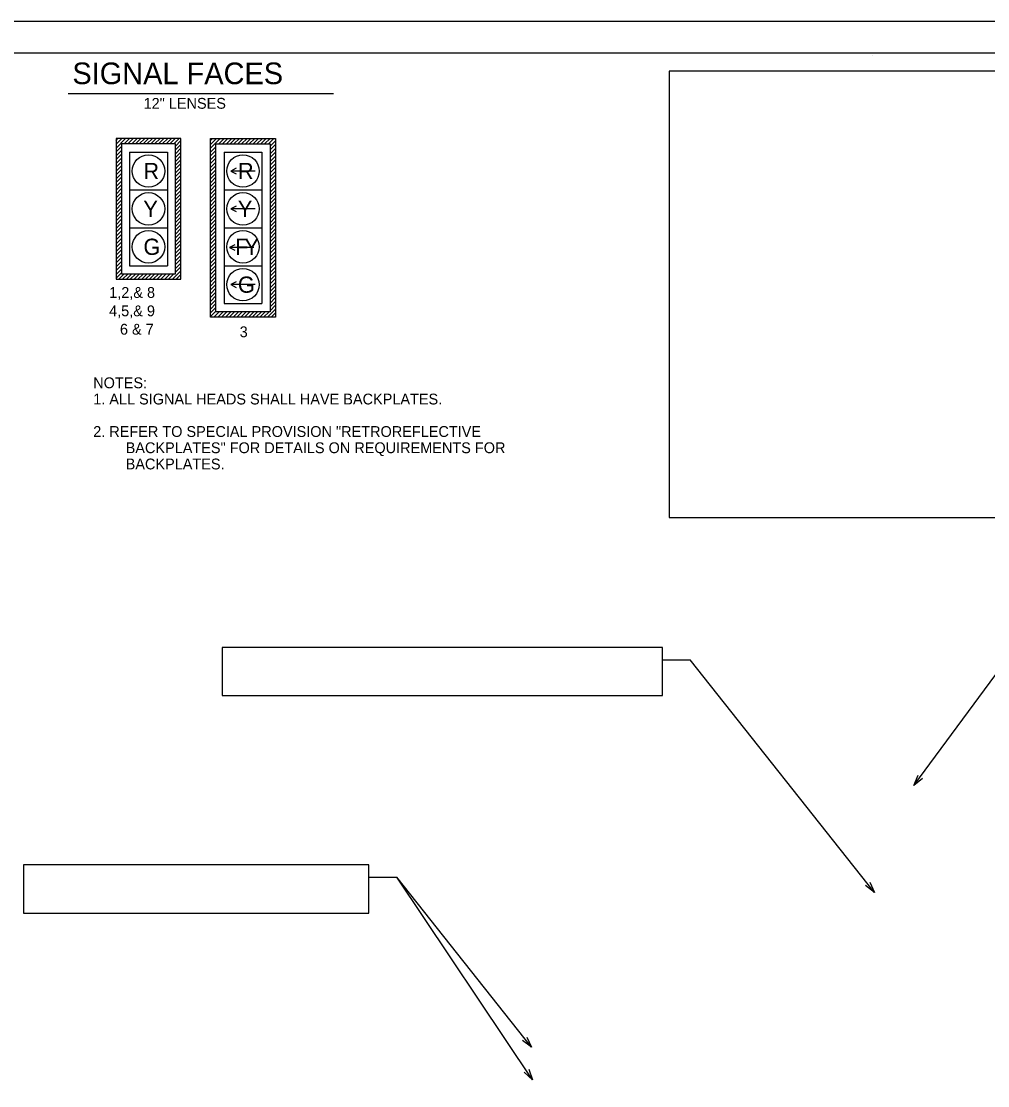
# Model space of a CAD drawing. Extents: x 1736833 to 1738623, y 544707 to 545544.
# Drawn here: x 1737803.3 to 1738160.6, y 544953.4 to 545346.8 of the extents above; entities that cross this region are included whole.
import ezdxf

# ---------------------------------------------------------------- set-up
doc = ezdxf.new("R2010")
doc.units = 0
for name, color, linetype in [('R_Border', 7, 'Continuous'), ('R_Draft', 7, 'Continuous'), ('R_No Plot', 7, 'Continuous'), ('T_Drafting', 7, 'Continuous'), ('T_Notes', 7, 'Continuous')]:
    doc.layers.add(name, color=color, linetype=linetype)

msp = doc.modelspace()

# ---------------------------------------------------------------- linework, layer by layer
at = {"layer": 'R_Border'}
for p, q in [((1737660.6, 545335.14), (1738609.14, 545335.14)), ((1738118.16, 545334.36), (1738118.16, 545334.36)), ((1738118.16, 545334.36), (1738118.16, 545334.36))]:
    msp.add_line(p, q, dxfattribs=at)
msp.add_lwpolyline([(1738042.88, 545163.45), (1738213.45, 545163.45), (1738213.45, 545328.38), (1738042.88, 545328.38)], close=True, dxfattribs=at)
at = {"layer": 'R_Draft'}
msp.add_lwpolyline([(1737660.6, 545335.14), (1738362.36, 545335.14), (1738362.36, 545305.5), (1738475, 545295.74), (1738536.2, 545296.37), (1738536.2, 545224.37), (1738536.2, 545185.59), (1738536.2, 545175.9), (1738608.92, 545175.9), (1738609.14, 544767.79), (1738408.07, 544767.79), (1738257.64, 544767.79), (1738257.64, 544719.22), (1737660.6, 544718.76)], close=True, dxfattribs=at)
at = {"layer": 'R_No Plot'}
msp.add_line((1737623.4, 545346.82), (1738623.4, 545346.82), dxfattribs=at)
msp.add_lwpolyline([(1737623.38, 545346.82), (1738623.4, 545346.82), (1738623.4, 544706.81), (1737623.38, 544706.81)], close=True, dxfattribs=at)
at = {"layer": 'T_Drafting'}
for p, q in [((1737862.36, 545303.48), (1737838.36, 545303.48)), ((1737838.36, 545303.48), (1737838.36, 545251.48)), ((1737838.36, 545299.93), (1737841.91, 545303.48)), ((1737838.36, 545301.35), (1737840.5, 545303.48)), ((1737838.36, 545302.76), (1737839.08, 545303.48)), ((1737841.32, 545301.48), (1737843.32, 545303.48)), ((1737842.74, 545301.48), (1737844.74, 545303.48)), ((1737844.15, 545301.48), (1737846.15, 545303.48)), ((1737845.57, 545301.48), (1737847.57, 545303.48)), ((1737846.98, 545301.48), (1737848.98, 545303.48)), ((1737848.4, 545301.48), (1737850.4, 545303.48)), ((1737849.81, 545301.48), (1737851.81, 545303.48)), ((1737851.22, 545301.48), (1737853.22, 545303.48)), ((1737852.64, 545301.48), (1737854.64, 545303.48)), ((1737854.05, 545301.48), (1737856.05, 545303.48)), ((1737855.47, 545301.48), (1737857.47, 545303.48)), ((1737856.88, 545301.48), (1737858.88, 545303.48)), ((1737858.29, 545301.48), (1737860.29, 545303.48)), ((1737859.71, 545301.48), (1737861.71, 545303.48)), ((1737860.36, 545300.72), (1737862.36, 545302.72)), ((1737862.36, 545251.48), (1737862.36, 545303.48)), ((1737873.3, 545237.48), (1737873.3, 545303.48)), ((1737873.3, 545303.48), (1737897.3, 545303.48)), ((1737873.3, 545299.87), (1737876.91, 545303.48)), ((1737873.3, 545301.29), (1737875.49, 545303.48)), ((1737873.3, 545302.7), (1737874.08, 545303.48)), ((1737876.32, 545301.48), (1737878.32, 545303.48)), ((1737877.74, 545301.48), (1737879.74, 545303.48)), ((1737879.15, 545301.48), (1737881.15, 545303.48)), ((1737880.56, 545301.48), (1737882.56, 545303.48)), ((1737881.98, 545301.48), (1737883.98, 545303.48)), ((1737883.39, 545301.48), (1737885.39, 545303.48)), ((1737884.81, 545301.48), (1737886.81, 545303.48)), ((1737886.22, 545301.48), (1737888.22, 545303.48)), ((1737887.64, 545301.48), (1737889.64, 545303.48)), ((1737889.05, 545301.48), (1737891.05, 545303.48)), ((1737890.46, 545301.48), (1737892.46, 545303.48)), ((1737891.88, 545301.48), (1737893.88, 545303.48)), ((1737893.29, 545301.48), (1737895.29, 545303.48)), ((1737894.71, 545301.48), (1737896.71, 545303.48)), ((1737895.3, 545300.66), (1737897.3, 545302.66)), ((1737897.3, 545303.48), (1737897.3, 545237.48)), ((1737838.36, 545298.52), (1737840.36, 545300.52)), ((1737838.36, 545297.1), (1737840.36, 545299.1)), ((1737843.36, 545298.48), (1737857.36, 545298.48)), ((1737843.36, 545298.48), (1737843.36, 545284.48)), ((1737857.36, 545298.48), (1737857.36, 545284.48)), ((1737860.36, 545299.31), (1737862.36, 545301.31)), ((1737860.36, 545297.89), (1737862.36, 545299.89)), ((1737860.36, 545296.48), (1737862.36, 545298.48)), ((1737873.3, 545298.46), (1737875.3, 545300.46)), ((1737873.3, 545297.04), (1737875.3, 545299.04)), ((1737878.3, 545298.48), (1737892.3, 545298.48)), ((1737878.3, 545298.48), (1737878.3, 545284.48)), ((1737892.3, 545298.48), (1737892.3, 545284.48)), ((1737895.3, 545299.25), (1737897.3, 545301.25)), ((1737895.3, 545297.83), (1737897.3, 545299.83)), ((1737895.3, 545296.42), (1737897.3, 545298.42)), ((1737838.36, 545295.69), (1737840.36, 545297.69)), ((1737838.36, 545294.28), (1737840.36, 545296.28)), ((1737838.36, 545292.86), (1737840.36, 545294.86)), ((1737860.36, 545295.06), (1737862.36, 545297.06)), ((1737860.36, 545293.65), (1737862.36, 545295.65)), ((1737860.36, 545292.23), (1737862.36, 545294.23)), ((1737873.3, 545295.63), (1737875.3, 545297.63)), ((1737873.3, 545294.22), (1737875.3, 545296.22)), ((1737873.3, 545292.8), (1737875.3, 545294.8)), ((1737895.3, 545295), (1737897.3, 545297)), ((1737895.3, 545293.59), (1737897.3, 545295.59)), ((1737895.3, 545292.17), (1737897.3, 545294.17)), ((1737838.36, 545291.45), (1737840.36, 545293.45)), ((1737838.36, 545290.03), (1737840.36, 545292.03)), ((1737838.36, 545288.62), (1737840.36, 545290.62)), ((1737860.36, 545290.82), (1737862.36, 545292.82)), ((1737860.36, 545289.41), (1737862.36, 545291.41)), ((1737873.3, 545291.39), (1737875.3, 545293.39)), ((1737873.3, 545289.97), (1737875.3, 545291.97)), ((1737873.3, 545288.56), (1737875.3, 545290.56)), ((1737889.8, 545291.48), (1737880.8, 545291.48)), ((1737895.3, 545290.76), (1737897.3, 545292.76)), ((1737895.3, 545289.35), (1737897.3, 545291.35)), ((1737838.36, 545287.21), (1737840.36, 545289.21)), ((1737838.36, 545285.79), (1737840.36, 545287.79)), ((1737838.36, 545284.38), (1737840.36, 545286.38)), ((1737860.36, 545287.99), (1737862.36, 545289.99)), ((1737860.36, 545286.58), (1737862.36, 545288.58)), ((1737860.36, 545285.16), (1737862.36, 545287.16)), ((1737873.3, 545287.15), (1737875.3, 545289.15)), ((1737873.3, 545285.73), (1737875.3, 545287.73)), ((1737873.3, 545284.32), (1737875.3, 545286.32)), ((1737895.3, 545287.93), (1737897.3, 545289.93)), ((1737895.3, 545286.52), (1737897.3, 545288.52)), ((1737895.3, 545285.1), (1737897.3, 545287.1)), ((1737838.36, 545282.96), (1737840.36, 545284.96)), ((1737838.36, 545281.55), (1737840.36, 545283.55)), ((1737843.36, 545284.48), (1737857.36, 545284.48)), ((1737843.36, 545284.48), (1737843.36, 545270.48)), ((1737857.36, 545284.48), (1737857.36, 545270.48)), ((1737860.36, 545283.75), (1737862.36, 545285.75)), ((1737860.36, 545282.34), (1737862.36, 545284.34)), ((1737860.36, 545280.92), (1737862.36, 545282.92)), ((1737873.3, 545282.9), (1737875.3, 545284.9)), ((1737873.3, 545281.49), (1737875.3, 545283.49)), ((1737878.3, 545284.48), (1737892.3, 545284.48)), ((1737878.3, 545284.48), (1737878.3, 545270.48)), ((1737892.3, 545284.48), (1737892.3, 545270.48)), ((1737895.3, 545283.69), (1737897.3, 545285.69)), ((1737895.3, 545282.28), (1737897.3, 545284.28)), ((1737895.3, 545280.86), (1737897.3, 545282.86)), ((1737838.36, 545280.13), (1737840.36, 545282.13)), ((1737838.36, 545278.72), (1737840.36, 545280.72)), ((1737838.36, 545277.31), (1737840.36, 545279.31)), ((1737860.36, 545279.51), (1737862.36, 545281.51)), ((1737860.36, 545278.09), (1737862.36, 545280.09)), ((1737860.36, 545276.68), (1737862.36, 545278.68)), ((1737873.3, 545280.07), (1737875.3, 545282.07)), ((1737873.3, 545278.66), (1737875.3, 545280.66)), ((1737873.3, 545277.25), (1737875.3, 545279.25)), ((1737895.3, 545279.45), (1737897.3, 545281.45)), ((1737895.3, 545278.03), (1737897.3, 545280.03)), ((1737895.3, 545276.62), (1737897.3, 545278.62)), ((1737838.36, 545275.89), (1737840.36, 545277.89)), ((1737838.36, 545274.48), (1737840.36, 545276.48)), ((1737838.36, 545273.06), (1737840.36, 545275.06)), ((1737860.36, 545275.26), (1737862.36, 545277.26)), ((1737860.36, 545273.85), (1737862.36, 545275.85)), ((1737873.3, 545275.83), (1737875.3, 545277.83)), ((1737873.3, 545274.42), (1737875.3, 545276.42)), ((1737873.3, 545273), (1737875.3, 545275)), ((1737889.8, 545277.48), (1737880.8, 545277.48)), ((1737895.3, 545275.2), (1737897.3, 545277.2)), ((1737895.3, 545273.79), (1737897.3, 545275.79)), ((1737838.36, 545271.65), (1737840.36, 545273.65)), ((1737838.36, 545270.23), (1737840.36, 545272.23)), ((1737838.36, 545268.82), (1737840.36, 545270.82)), ((1737860.36, 545272.44), (1737862.36, 545274.44)), ((1737860.36, 545271.02), (1737862.36, 545273.02)), ((1737860.36, 545269.61), (1737862.36, 545271.61)), ((1737873.3, 545271.59), (1737875.3, 545273.59)), ((1737873.3, 545270.17), (1737875.3, 545272.17)), ((1737873.3, 545268.76), (1737875.3, 545270.76)), ((1737895.3, 545272.38), (1737897.3, 545274.38)), ((1737895.3, 545270.96), (1737897.3, 545272.96)), ((1737895.3, 545269.55), (1737897.3, 545271.55)), ((1737838.36, 545267.41), (1737840.36, 545269.41)), ((1737838.36, 545265.99), (1737840.36, 545267.99)), ((1737843.36, 545270.48), (1737857.36, 545270.48)), ((1737843.36, 545270.48), (1737843.36, 545256.48)), ((1737857.36, 545270.48), (1737857.36, 545256.48)), ((1737860.36, 545268.19), (1737862.36, 545270.19)), ((1737860.36, 545266.78), (1737862.36, 545268.78)), ((1737860.36, 545265.36), (1737862.36, 545267.36)), ((1737873.3, 545267.35), (1737875.3, 545269.35)), ((1737873.3, 545265.93), (1737875.3, 545267.93)), ((1737878.3, 545270.48), (1737892.3, 545270.48)), ((1737878.3, 545270.48), (1737878.3, 545256.48)), ((1737892.3, 545270.48), (1737892.3, 545256.48)), ((1737895.3, 545268.13), (1737897.3, 545270.13)), ((1737895.3, 545266.72), (1737897.3, 545268.72)), ((1737895.3, 545265.3), (1737897.3, 545267.3)), ((1737838.36, 545264.58), (1737840.36, 545266.58)), ((1737838.36, 545263.16), (1737840.36, 545265.16)), ((1737838.36, 545261.75), (1737840.36, 545263.75)), ((1737860.36, 545263.95), (1737862.36, 545265.95)), ((1737860.36, 545262.54), (1737862.36, 545264.54)), ((1737860.36, 545261.12), (1737862.36, 545263.12)), ((1737873.3, 545264.52), (1737875.3, 545266.52)), ((1737873.3, 545263.1), (1737875.3, 545265.1)), ((1737873.3, 545261.69), (1737875.3, 545263.69)), ((1737889.28, 545263.2), (1737880.28, 545263.2)), ((1737895.3, 545263.89), (1737897.3, 545265.89)), ((1737895.3, 545262.48), (1737897.3, 545264.48)), ((1737895.3, 545261.06), (1737897.3, 545263.06)), ((1737838.36, 545260.34), (1737840.36, 545262.34)), ((1737838.36, 545258.92), (1737840.36, 545260.92)), ((1737838.36, 545257.51), (1737840.36, 545259.51)), ((1737860.36, 545259.71), (1737862.36, 545261.71)), ((1737860.36, 545258.29), (1737862.36, 545260.29)), ((1737860.36, 545256.88), (1737862.36, 545258.88)), ((1737873.3, 545260.28), (1737875.3, 545262.28)), ((1737873.3, 545258.86), (1737875.3, 545260.86)), ((1737873.3, 545257.45), (1737875.3, 545259.45)), ((1737895.3, 545259.65), (1737897.3, 545261.65)), ((1737895.3, 545258.23), (1737897.3, 545260.23)), ((1737895.3, 545256.82), (1737897.3, 545258.82)), ((1737838.36, 545256.09), (1737840.36, 545258.09)), ((1737838.36, 545254.68), (1737840.36, 545256.68)), ((1737838.36, 545253.26), (1737840.36, 545255.26)), ((1737843.36, 545256.48), (1737857.36, 545256.48)), ((1737860.36, 545255.47), (1737862.36, 545257.47)), ((1737860.36, 545254.05), (1737862.36, 545256.05)), ((1737873.3, 545256.03), (1737875.3, 545258.03)), ((1737873.3, 545254.62), (1737875.3, 545256.62)), ((1737873.3, 545253.2), (1737875.3, 545255.2)), ((1737878.3, 545256.48), (1737892.3, 545256.48)), ((1737878.3, 545256.48), (1737878.3, 545242.48)), ((1737892.3, 545256.48), (1737892.3, 545242.48)), ((1737895.3, 545255.41), (1737897.3, 545257.41)), ((1737895.3, 545253.99), (1737897.3, 545255.99)), ((1737838.36, 545251.85), (1737840.36, 545253.85)), ((1737838.36, 545251.48), (1737862.36, 545251.48)), ((1737839.41, 545251.48), (1737841.41, 545253.48)), ((1737840.82, 545251.48), (1737842.82, 545253.48)), ((1737842.24, 545251.48), (1737844.24, 545253.48)), ((1737843.65, 545251.48), (1737845.65, 545253.48)), ((1737845.06, 545251.48), (1737847.06, 545253.48)), ((1737846.48, 545251.48), (1737848.48, 545253.48)), ((1737847.89, 545251.48), (1737849.89, 545253.48)), ((1737849.31, 545251.48), (1737851.31, 545253.48)), ((1737850.72, 545251.48), (1737852.72, 545253.48)), ((1737852.14, 545251.48), (1737854.14, 545253.48)), ((1737853.55, 545251.48), (1737855.55, 545253.48)), ((1737854.96, 545251.48), (1737856.96, 545253.48)), ((1737856.38, 545251.48), (1737858.38, 545253.48)), ((1737857.79, 545251.48), (1737859.79, 545253.48)), ((1737859.21, 545251.48), (1737862.36, 545254.64)), ((1737860.62, 545251.48), (1737862.36, 545253.22)), ((1737862.03, 545251.48), (1737862.36, 545251.81)), ((1737873.3, 545251.79), (1737875.3, 545253.79)), ((1737873.3, 545250.38), (1737875.3, 545252.38)), ((1737873.3, 545248.96), (1737875.3, 545250.96)), ((1737895.3, 545252.58), (1737897.3, 545254.58)), ((1737895.3, 545251.16), (1737897.3, 545253.16)), ((1737895.3, 545249.75), (1737897.3, 545251.75)), ((1737873.3, 545247.55), (1737875.3, 545249.55)), ((1737873.3, 545246.13), (1737875.3, 545248.13)), ((1737889.8, 545249.48), (1737880.8, 545249.48)), ((1737895.3, 545248.33), (1737897.3, 545250.33)), ((1737895.3, 545246.92), (1737897.3, 545248.92)), ((1737895.3, 545245.51), (1737897.3, 545247.51)), ((1737873.3, 545244.72), (1737875.3, 545246.72)), ((1737873.3, 545243.3), (1737875.3, 545245.3)), ((1737873.3, 545241.89), (1737875.3, 545243.89)), ((1737895.3, 545244.09), (1737897.3, 545246.09)), ((1737895.3, 545242.68), (1737897.3, 545244.68)), ((1737895.3, 545241.26), (1737897.3, 545243.26)), ((1737873.3, 545240.48), (1737875.3, 545242.48)), ((1737873.3, 545239.06), (1737875.3, 545241.06)), ((1737873.3, 545237.65), (1737875.3, 545239.65)), ((1737874.55, 545237.48), (1737876.55, 545239.48)), ((1737875.96, 545237.48), (1737877.96, 545239.48)), ((1737877.38, 545237.48), (1737879.38, 545239.48)), ((1737878.3, 545242.48), (1737892.3, 545242.48)), ((1737878.79, 545237.48), (1737880.79, 545239.48)), ((1737880.2, 545237.48), (1737882.2, 545239.48)), ((1737881.62, 545237.48), (1737883.62, 545239.48)), ((1737883.03, 545237.48), (1737885.03, 545239.48)), ((1737884.45, 545237.48), (1737886.45, 545239.48)), ((1737885.86, 545237.48), (1737887.86, 545239.48)), ((1737887.28, 545237.48), (1737889.28, 545239.48)), ((1737888.69, 545237.48), (1737890.69, 545239.48)), ((1737890.1, 545237.48), (1737892.1, 545239.48)), ((1737891.52, 545237.48), (1737893.52, 545239.48)), ((1737892.93, 545237.48), (1737894.93, 545239.48)), ((1737894.35, 545237.48), (1737897.3, 545240.43)), ((1737895.3, 545239.85), (1737897.3, 545241.85)), ((1737897.3, 545237.48), (1737873.3, 545237.48)), ((1737895.76, 545237.48), (1737897.3, 545239.02)), ((1737897.18, 545237.48), (1737897.3, 545237.61)), ((1738133.29, 545064.35), (1738185.6, 545135.24)), ((1738040.37, 545110.87), (1738050.68, 545110.87)), ((1738118.74, 545024.86), (1738050.68, 545110.87)), ((1737931.83, 545030.54), (1737942.13, 545030.54)), ((1737991.93, 544967.6), (1737942.13, 545030.54)), ((1737992.33, 544955.61), (1737942.13, 545030.54))]:
    msp.add_line(p, q, dxfattribs=at)
for points in [[(1737860.36, 545253.48), (1737860.36, 545301.48), (1737840.36, 545301.48), (1737840.36, 545253.48)], [(1737875.3, 545239.48), (1737875.3, 545301.48), (1737895.3, 545301.48), (1737895.3, 545239.48)], [(1737877.61, 545097.58), (1738040.37, 545097.58), (1738040.37, 545115.38), (1737877.61, 545115.38)], [(1737804.22, 545017.24), (1737931.83, 545017.24), (1737931.83, 545035.04), (1737804.22, 545035.04)]]:
    msp.add_lwpolyline(points, close=True, dxfattribs=at)
for points in [[(1737882.8, 545292.48), (1737880.8, 545291.48), (1737882.8, 545290.48)], [(1737882.8, 545278.48), (1737880.8, 545277.48), (1737882.8, 545276.48)], [(1737882.28, 545264.2), (1737880.28, 545263.2), (1737882.28, 545262.2)], [(1737882.8, 545250.48), (1737880.8, 545249.48), (1737882.8, 545248.48)], [(1738136.47, 545066.97), (1738133.29, 545064.35), (1738134.86, 545068.16)], [(1738117.05, 545028.61), (1738118.74, 545024.86), (1738115.48, 545027.37)], [(1737990.24, 544971.36), (1737991.93, 544967.6), (1737988.67, 544970.12)], [(1737990.94, 544959.49), (1737992.33, 544955.61), (1737989.28, 544958.37)]]:
    msp.add_lwpolyline(points, dxfattribs=at)
for centre in [(1737850.36, 545291.48), (1737885.3, 545291.48), (1737850.36, 545277.48), (1737885.3, 545277.48), (1737850.36, 545263.48), (1737885.3, 545263.48), (1737885.3, 545249.48)]:
    msp.add_circle(centre, 6, dxfattribs=at)
at = {"layer": 'T_Notes'}
msp.add_line((1737820.64, 545320.11), (1737918.82, 545320.11), dxfattribs=at)

# ---------------------------------------------------------------- texts
at = {"layer": 'T_Drafting'}
msp.add_text('12" LENSES', height=4, rotation=0.072, dxfattribs=at).set_placement((1737848.56, 545314.47))
for s, p in [('R', (1737848.5, 545288.48)), ('R', (1737883.44, 545288.48)), ('Y', (1737848.47, 545274.48)), ('Y', (1737883.41, 545274.48)), ('G', (1737848.5, 545260.48)), ('F', (1737882.4, 545260.48)), ('Y', (1737885.82, 545260.48)), ('G', (1737883.43, 545246.48))]:
    msp.add_text(s, height=6, dxfattribs=at).set_placement(p)
at = {"layer": 'T_Notes'}
for s, height, p in [('SIGNAL FACES', 8, (1737822.24, 545323.58)), ('1,2,& 8', 4, (1737835.84, 545244.6)), ('4,5,& 9', 4, (1737835.81, 545237.8)), ('6 & 7', 4, (1737839.82, 545231)), ('3', 4, (1737884.08, 545230.05)), ('NOTES:', 4, (1737829.93, 545211.2)), ('1. ALL SIGNAL HEADS SHALL HAVE BACKPLATES.', 4, (1737829.93, 545205.2)), ('2. REFER TO SPECIAL PROVISION "RETROREFLECTIVE', 4, (1737829.93, 545193.2)), ('BACKPLATES" FOR DETAILS ON REQUIREMENTS FOR ', 4, (1737841.93, 545187.2)), ('BACKPLATES.', 4, (1737841.93, 545181.2))]:
    msp.add_text(s, height=height, dxfattribs=at).set_placement(p)

doc.saveas('drawing.dxf')
